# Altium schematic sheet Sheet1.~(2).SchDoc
size A; SheetNumber: 1; SheetTotal: 1
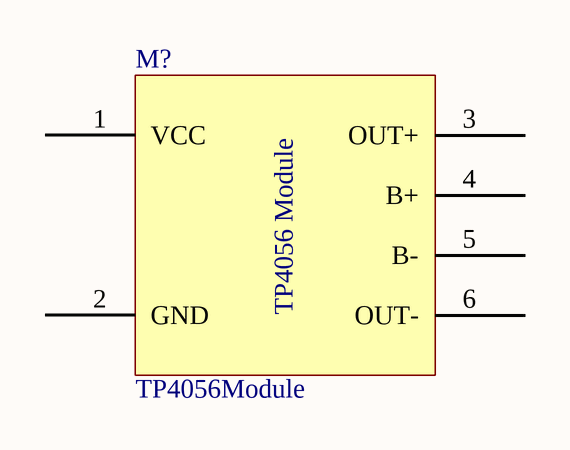
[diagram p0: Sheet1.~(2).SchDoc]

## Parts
M?  TP4056Module  [TP4056Module]

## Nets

Not connected (* = marked no-connect by the designer): M? 1(VCC) 2(GND) 3(OUT+) 4(B+) 5(B-) 6(OUT-)

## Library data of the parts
M? = TP4056Module: TP4056 Module for managing battery charging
